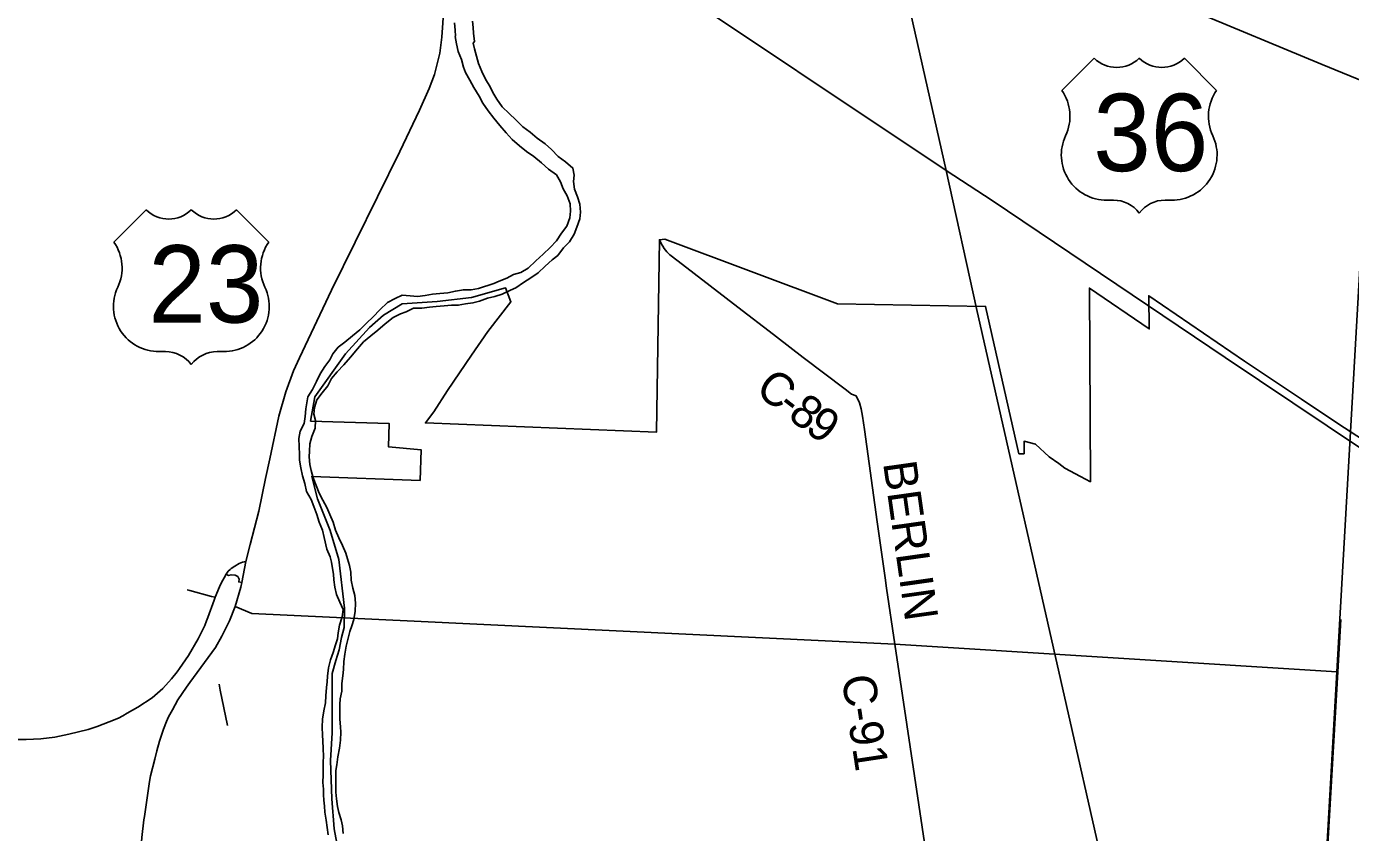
# Model space of a CAD drawing. Extents: x 1674899 to 2057726, y 653888 to 988278.
# Drawn here: x 1808187 to 1820096, y 828890 to 836141 of the extents above; entities that cross this region are included whole.
import ezdxf

# ---------------------------------------------------------------- set-up
doc = ezdxf.new("R2010")
doc.units = 0
for name, color, linetype in [('GM_P_County_Alignment', 7, 'Continuous'), ('GM_P_Township_Alignment', 7, 'Continuous'), ('GM_X_Corporation', 7, 'Continuous'), ('GM_X_County_Road', 7, 'Continuous'), ('GM_X_County_Road_Text', 7, 'Continuous'), ('GM_X_Interchange_Ramps', 7, 'Continuous'), ('GM_X_Major_River', 7, 'Continuous'), ('GM_X_Rail_Line', 7, 'Continuous'), ('GM_X_Township', 7, 'Continuous'), ('GM_X_US_Location', 7, 'Continuous'), ('GM_X_US_Route', 7, 'Continuous'), ('GM_X_US_Shield', 7, 'Continuous'), ('SH_Data', 7, 'Continuous')]:
    doc.layers.add(name, color=color, linetype=linetype)

msp = doc.modelspace()

# ---------------------------------------------------------------- linework, layer by layer
at = {"layer": 'GM_P_County_Alignment'}
msp.add_lwpolyline([(1810064, 830924), (1810215, 830861), (1811673, 830792), (1815997, 830585), (1819973, 830336), (1819982, 830336)], dxfattribs=at)
at = {"layer": 'GM_P_Township_Alignment'}
msp.add_lwpolyline([(1818191, 812181), (1818677, 812535), (1818724, 812578), (1818841, 812687), (1818912, 812752), (1818953, 812814), (1818968, 812896), (1819169, 816826), (1819403, 820562), (1819571, 823253), (1819982, 830336), (1820010, 830806)], dxfattribs=at)
at = {"layer": 'GM_X_Corporation'}
msp.add_lwpolyline([(1824031, 829939), (1819982, 832569), (1819654, 832789), (1819142, 833130), (1818281, 833718), (1818286, 833421), (1817747, 833788), (1817756, 832046), (1817667, 832094), (1817528, 832169), (1817473, 832209), (1817387, 832271), (1817263, 832384), (1817160, 832409), (1817160, 832297), (1817114, 832297), (1816814, 833623), (1815483, 833646), (1813930, 834229), (1813880, 834222), (1813853, 832491), (1811776, 832575), (1811850, 832675), (1811974, 832866), (1812189, 833183), (1812337, 833398), (1812545, 833665), (1812495, 833790), (1812189, 833704), (1811881, 833666), (1811566, 833646), (1811397, 833543), (1811273, 833433), (1811057, 833195), (1810780, 832810), (1810743, 832591), (1811450, 832568), (1811442, 832360), (1811738, 832332), (1811727, 832058), (1810753, 832094), (1810804, 831891), (1810920, 831606), (1810996, 831345), (1811047, 830907), (1811046, 830734), (1811021, 830645), (1811000, 830534), (1810970, 830437), (1810937, 830321), (1810936, 829787), (1810922, 829539), (1810934, 829192), (1810954, 828923), (1811004, 828664)], dxfattribs=at)
at = {"layer": 'GM_X_County_Road'}
for points in [[(1813910, 834164), (1813898, 834183), (1813880, 834222)], [(1815650, 832818), (1815609, 832834), (1815550, 832877), (1815172, 833164), (1814933, 833350), (1814868, 833401), (1814625, 833586), (1814048, 834029), (1813975, 834088), (1813947, 834115), (1813922, 834145), (1813910, 834164)], [(1815650, 832818), (1815681, 832754), (1815696, 832701), (1815707, 832636), (1815724, 832514), (1815839, 831685), (1815910, 831182), (1815924, 831087), (1815997, 830585), (1816596, 826570), (1816611, 826462)], [(1809930, 830171), (1809919, 830224)], [(1809995, 829854), (1809930, 830171), (1809930, 830171)]]:
    msp.add_lwpolyline(points, dxfattribs=at)
at = {"layer": 'GM_X_Interchange_Ramps'}
for points in [[(1809982, 831214), (1810003, 831202), (1810028, 831209), (1810065, 831206), (1810087, 831192), (1810100, 831170), (1810097, 831145), (1810123, 831139)], [(1809883, 831007), (1809852, 831014), (1809658, 831067), (1809633, 831074)]]:
    msp.add_lwpolyline(points, dxfattribs=at)
at = {"layer": 'GM_X_Major_River'}
for points in [[(1812037, 836175), (1812042, 836109), (1812046, 836055)], [(1812218, 836006), (1812208, 836082), (1812205, 836132), (1812199, 836188)], [(1812046, 836055), (1812044, 836051), (1812055, 835985), (1812069, 835915), (1812100, 835844), (1812118, 835776), (1812137, 835726), (1812175, 835658), (1812212, 835591), (1812260, 835513), (1812291, 835450), (1812341, 835382), (1812392, 835317), (1812444, 835249), (1812503, 835184), (1812557, 835124), (1812622, 835067), (1812686, 835015), (1812751, 834970), (1812819, 834915), (1812884, 834857), (1812954, 834808), (1812989, 834744), (1813013, 834680), (1813050, 834617), (1813078, 834547), (1813079, 834481), (1813075, 834419), (1813048, 834345), (1813000, 834281), (1812953, 834213), (1812899, 834152), (1812834, 834092), (1812768, 834034), (1812701, 833967), (1812635, 833929), (1812569, 833910), (1812507, 833878), (1812440, 833849), (1812390, 833829), (1812252, 833784), (1812186, 833773), (1812118, 833773), (1812046, 833760), (1811976, 833744), (1811904, 833739), (1811840, 833733), (1811773, 833720), (1811705, 833712), (1811637, 833719), (1811565, 833723), (1811503, 833694), (1811435, 833658), (1811364, 833593), (1811306, 833529), (1811245, 833471), (1811185, 833412), (1811121, 833358), (1811052, 833301), (1810990, 833255), (1810943, 833197), (1810915, 833143), (1810870, 833082), (1810828, 833016), (1810795, 832946), (1810759, 832876), (1810718, 832810), (1810708, 832756), (1810699, 832700), (1810693, 832632), (1810684, 832568), (1810648, 832499), (1810637, 832433), (1810641, 832362), (1810642, 832290), (1810644, 832240), (1810655, 832172), (1810669, 832100), (1810690, 832030), (1810707, 831959), (1810747, 831887), (1810772, 831823), (1810800, 831750), (1810821, 831682), (1810849, 831610), (1810866, 831544), (1810889, 831439), (1810919, 831371), (1810932, 831321), (1810940, 831265), (1810949, 831214), (1810953, 831164), (1810960, 831098), (1810976, 831032), (1811007, 830962), (1811035, 830897), (1811026, 830829), (1811004, 830755), (1810991, 830687), (1810985, 830631), (1810968, 830579)], [(1811077, 830625), (1811095, 830697), (1811114, 830748), (1811132, 830806), (1811145, 830880), (1811147, 830952), (1811142, 831021), (1811124, 831089), (1811109, 831159), (1811104, 831231), (1811094, 831291), (1811076, 831352), (1811061, 831402), (1811031, 831472), (1810998, 831540), (1810967, 831611), (1810945, 831683), (1810916, 831751), (1810890, 831814), (1810853, 831880), (1810821, 831942), (1810792, 832011), (1810766, 832081), (1810749, 832147), (1810735, 832201), (1810730, 832270), (1810732, 832320), (1810735, 832388), (1810753, 832452), (1810784, 832528), (1810787, 832596), (1810771, 832652), (1810779, 832714), (1810800, 832782), (1810846, 832844), (1810897, 832907), (1810932, 832973), (1810982, 833033), (1811041, 833096), (1811101, 833166), (1811164, 833240), (1811218, 833303), (1811285, 833359), (1811349, 833410), (1811413, 833466), (1811484, 833522), (1811552, 833555), (1811602, 833575), (1811669, 833606), (1811743, 833608), (1811811, 833617), (1811873, 833623), (1811943, 833628), (1812009, 833634), (1812071, 833633), (1812137, 833647), (1812203, 833654), (1812263, 833670), (1812335, 833697), (1812399, 833711), (1812465, 833734), (1812540, 833768), (1812590, 833791), (1812658, 833837), (1812723, 833881), (1812791, 833926), (1812853, 833984), (1812916, 834043), (1812966, 834081), (1813017, 834149), (1813071, 834204), (1813112, 834272), (1813136, 834336), (1813165, 834410), (1813171, 834472), (1813164, 834542), (1813144, 834610), (1813117, 834677), (1813107, 834747), (1813114, 834803), (1813102, 834867), (1813035, 834924), (1812969, 834970), (1812910, 835033), (1812852, 835085), (1812781, 835136), (1812717, 835189), (1812651, 835237), (1812588, 835300), (1812530, 835358), (1812465, 835419), (1812417, 835487), (1812382, 835548), (1812358, 835598), (1812315, 835666), (1812283, 835735), (1812254, 835807), (1812236, 835875), (1812217, 835940), (1812205, 835990), (1812218, 836006)], [(1810968, 830579), (1810946, 830509), (1810923, 830442), (1810905, 830370), (1810896, 830296), (1810892, 830245), (1810887, 830193), (1810879, 830119), (1810878, 830057), (1810861, 829983), (1810851, 829911), (1810846, 829837), (1810850, 829765), (1810853, 829715), (1810857, 829647), (1810858, 829575), (1810856, 829525), (1810857, 829461), (1810857, 829409), (1810854, 829341), (1810858, 829280), (1810859, 829230), (1810863, 829180), (1810869, 829128), (1810872, 829072), (1810882, 829002), (1810893, 828936), (1810902, 828868)], [(1811035, 828882), (1811029, 828951), (1811018, 829003), (1810996, 829069), (1810985, 829125), (1810975, 829193), (1810970, 829252), (1810970, 829304), (1810969, 829380), (1810971, 829448), (1810978, 829500), (1810988, 829570), (1811003, 829650), (1811013, 829720), (1811014, 829792), (1811012, 829842), (1811007, 829910), (1811007, 829982), (1811006, 830042), (1811010, 830092), (1811023, 830160), (1811025, 830230), (1811034, 830300), (1811038, 830356), (1811043, 830429), (1811052, 830495), (1811064, 830567), (1811077, 830625)]]:
    msp.add_lwpolyline(points, dxfattribs=at)
at = {"layer": 'GM_X_Rail_Line'}
for points in [[(1816458, 834846), (1816035, 836736), (1815982, 837005), (1815947, 837207), (1815926, 837361), (1815895, 837598), (1815753, 838938), (1815653, 839903), (1815614, 840276)], [(1816458, 834846), (1813782, 836635), (1813586, 836766), (1813453, 836855), (1813365, 836915), (1813313, 836952), (1813257, 836995), (1813207, 837037), (1813166, 837075), (1813129, 837113), (1813084, 837165), (1813038, 837220), (1812994, 837287), (1812951, 837359), (1812925, 837406), (1812892, 837481), (1812865, 837548), (1812835, 837637), (1812816, 837699), (1812792, 837794), (1812773, 837886), (1812754, 838013), (1812743, 838132)], [(1824823, 828274), (1824798, 828530), (1824780, 828625), (1824761, 828707), (1824735, 828803), (1824703, 828897), (1824668, 828982), (1824633, 829064), (1824584, 829157), (1824531, 829246), (1824457, 829354), (1824395, 829433), (1824336, 829501), (1824280, 829561), (1824214, 829625), (1824146, 829684), (1824084, 829735), (1823989, 829805), (1823470, 830155), (1821102, 831734), (1818968, 833163), (1816874, 834575), (1816458, 834846)], [(1819669, 823784), (1819294, 824246), (1819090, 824554), (1818808, 825089), (1818651, 825456), (1818533, 825770), (1818395, 826257), (1817593, 829809), (1816732, 833603), (1816458, 834846)]]:
    msp.add_lwpolyline(points, dxfattribs=at)
at = {"layer": 'GM_X_Township'}
for points in [[(1805038, 848430), (1809012, 848241), (1810328, 848152), (1816586, 847751), (1820950, 847472), (1820789, 844650), (1820411, 838018), (1820357, 837080), (1820274, 835623), (1820182, 834021), (1820000, 830812), (1819973, 830336), (1819571, 823253), (1819403, 820562), (1817422, 820661), (1816437, 820719), (1811977, 820984), (1811439, 820998), (1810371, 821059), (1808814, 821113), (1806012, 821223)], [(1818966, 812859), (1819169, 816826), (1819403, 820562), (1819571, 823253), (1819973, 830336), (1820000, 830812), (1820182, 834021), (1820873, 833984), (1824840, 833781), (1824931, 833776), (1825545, 833759), (1825602, 833752), (1827748, 833636), (1831529, 833453), (1832327, 833414), (1835297, 833263)]]:
    msp.add_lwpolyline(points, dxfattribs=at)
at = {"layer": 'GM_X_US_Route'}
for points in [[(1810375, 832252), (1810458, 832634), (1810519, 832855), (1810590, 833042), (1810642, 833161), (1810931, 833769), (1811145, 834201), (1811545, 835017), (1811721, 835387), (1811810, 835583), (1811858, 835709), (1811904, 835901), (1811923, 836046), (1811940, 836302), (1811943, 836419), (1811905, 836674), (1811861, 836825), (1811798, 837006), (1811769, 837090), (1811671, 837289), (1811535, 837559), (1811464, 837713)], [(1818221, 836484), (1818657, 836290), (1819840, 835798), (1820274, 835623), (1820373, 835583), (1821164, 835274), (1821658, 835092), (1821742, 835058)], [(1810200, 831481), (1810278, 831782), (1810336, 832074), (1810375, 832252)], [(1810161, 831327), (1810200, 831481)], [(1809658, 830240), (1809887, 830554), (1809944, 830656), (1810013, 830794), (1810064, 830924), (1810114, 831096), (1810123, 831139), (1810161, 831327)], [(1809806, 830793), (1809817, 830824), (1809875, 830980), (1809883, 831007), (1809924, 831101), (1809942, 831139), (1809965, 831182), (1809982, 831214), (1810002, 831240), (1810018, 831255)], [(1810018, 831255), (1810029, 831264), (1810062, 831287), (1810099, 831310), (1810129, 831322), (1810161, 831327)], [(1809565, 830366), (1809645, 830481), (1809731, 830633), (1809791, 830753), (1809806, 830793)], [(1809054, 829941), (1809092, 829962), (1809190, 830018), (1809319, 830101), (1809414, 830184), (1809493, 830273), (1809544, 830335), (1809565, 830366)], [(1809448, 829889), (1809465, 829932), (1809500, 829994), (1809550, 830083), (1809626, 830197), (1809658, 830240)], [(1806492, 829835), (1807414, 829767), (1807797, 829742), (1807937, 829731), (1808063, 829726), (1808184, 829726), (1808317, 829734), (1808441, 829749), (1808567, 829774), (1808741, 829816), (1808822, 829845), (1808931, 829885), (1809015, 829920), (1809054, 829941)], [(1809341, 829549), (1809360, 829624), (1809385, 829713), (1809419, 829819), (1809448, 829889)], [(1809303, 829401), (1809341, 829549)], [(1809248, 829033), (1809295, 829348)], [(1809295, 829348), (1809303, 829401)], [(1809185, 828132), (1809189, 828331), (1809196, 828477), (1809207, 828601), (1809226, 828846), (1809244, 829004), (1809248, 829033)]]:
    msp.add_lwpolyline(points, dxfattribs=at)
at = {"layer": 'GM_X_US_Shield'}
for p, q in [((1817790, 835856), (1817500, 835565)), ((1818892, 835565), (1818602, 835856)), ((1817906, 834579), (1817964, 834579)), ((1818428, 834579), (1818486, 834579)), ((1809264, 834492), (1808974, 834202)), ((1810366, 834202), (1810076, 834492)), ((1809380, 833216), (1809438, 833216)), ((1809902, 833216), (1809960, 833216))]:
    msp.add_line(p, q, dxfattribs=at)
for centre, radius, start, end in [((1817993, 836063), 290, 225.573, 314.427), ((1818399, 836063), 290, 225.573, 314.427), ((1817167, 835333), 406, 334.5471, 35.0009), ((1819224, 835333), 406, 144.9991, 205.4529), ((1817901, 834985), 406, 154.8319, 270.6383), ((1818490, 834985), 406, 269.3617, 25.1681), ((1817964, 834289), 290, 36.8699, 90), ((1818428, 834289), 290, 90, 143.1301), ((1809467, 834699), 290, 225.573, 314.427), ((1809873, 834699), 290, 225.573, 314.427), ((1808641, 833969), 406, 334.5471, 35.0009), ((1810699, 833969), 406, 144.9991, 205.4529), ((1809376, 833622), 406, 154.8319, 270.6383), ((1809965, 833622), 406, 269.3617, 25.1681), ((1809438, 832926), 290, 36.8699, 90), ((1809902, 832926), 290, 90, 143.1301)]:
    msp.add_arc(centre, radius, start, end, dxfattribs=at)
at = {"layer": 'SH_Data'}
for points in [[(1810375, 832252), (1810458, 832634), (1810519, 832855), (1810590, 833042), (1810642, 833161), (1810931, 833769), (1811145, 834201), (1811545, 835017), (1811721, 835387), (1811810, 835583), (1811858, 835709), (1811904, 835901), (1811923, 836046), (1811940, 836302), (1811943, 836419), (1811905, 836674), (1811861, 836825), (1811798, 837006), (1811769, 837090), (1811671, 837289), (1811535, 837559), (1811464, 837713)], [(1818221, 836484), (1818657, 836290), (1819840, 835798), (1820274, 835623), (1820373, 835583), (1821164, 835274), (1821658, 835092), (1821742, 835058)], [(1810200, 831481), (1810278, 831782), (1810336, 832074), (1810375, 832252)], [(1810161, 831327), (1810200, 831481)], [(1809658, 830240), (1809887, 830554), (1809944, 830656), (1810013, 830794), (1810064, 830924), (1810114, 831096), (1810123, 831139), (1810161, 831327)], [(1809054, 829941), (1809092, 829962), (1809190, 830018), (1809319, 830101), (1809414, 830184), (1809493, 830273), (1809544, 830335), (1809565, 830366)], [(1809448, 829889), (1809465, 829932), (1809500, 829994), (1809550, 830083), (1809626, 830197), (1809658, 830240)], [(1806492, 829835), (1807414, 829767), (1807797, 829742), (1807937, 829731), (1808063, 829726), (1808184, 829726), (1808317, 829734), (1808441, 829749), (1808567, 829774), (1808741, 829816), (1808822, 829845), (1808931, 829885), (1809015, 829920), (1809054, 829941)], [(1809341, 829549), (1809360, 829624), (1809385, 829713), (1809419, 829819), (1809448, 829889)], [(1809303, 829401), (1809341, 829549)], [(1809248, 829033), (1809295, 829348)], [(1809295, 829348), (1809303, 829401)], [(1809185, 828132), (1809189, 828331), (1809196, 828477), (1809207, 828601), (1809226, 828846), (1809244, 829004), (1809248, 829033)]]:
    msp.add_lwpolyline(points, dxfattribs=at)

# ---------------------------------------------------------------- texts
at = {"layer": 'GM_X_County_Road_Text'}
for s, rotation, p in [('C', 322.1692, (1814730, 832851)), ('-', 322.232, (1814925, 832700)), ('8', 322.4644, (1815024, 832624)), ('9', 324.4248, (1815179, 832504)), ('BERLIN', 278.0224, (1815891, 832214)), ('C-91', 278.6161, (1815518, 830289))]:
    msp.add_text(s, height=300, rotation=rotation, dxfattribs=at).set_placement(p)
at = {"layer": 'GM_X_US_Location'}
for s, p in [('0', (1819104, 836111)), ('/', (1819104, 836111)), ('0', (1810049, 830870)), ('/', (1810049, 830870))]:
    msp.add_text(s, height=1, dxfattribs=at).set_placement(p)
for s, p in [('36', (1818898, 835904)), ('23', (1809843, 830663))]:
    msp.add_text(s, height=1, rotation=0, dxfattribs=at).set_placement(p)
at = {"layer": 'GM_X_US_Shield'}
for s, p in [('36', (1817782, 834840)), ('23', (1809283, 833477))]:
    msp.add_text(s, height=696.1, dxfattribs=at).set_placement(p)

doc.saveas('drawing.dxf')
